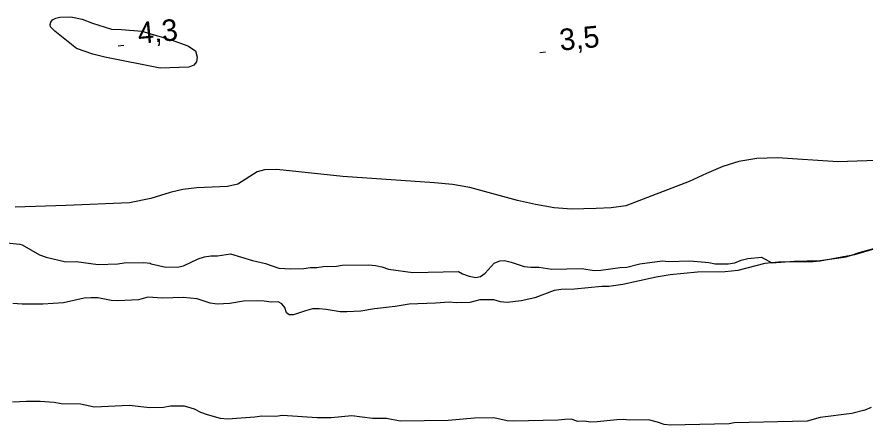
# Model space of a CAD drawing. Extents: x 336540 to 340074, y 5572036 to 5573747.
# Drawn here: x 336745.5 to 336863.5, y 5572306.6 to 5572363.4 of the extents above; entities that cross this region are included whole.
import ezdxf

# ---------------------------------------------------------------- set-up
doc = ezdxf.new("R2010")
doc.units = 0
for name, color, linetype in [('Niveau 2', 7, 'Continuous'), ('Niveau 3', 7, 'Continuous'), ('Niveau 4', 7, 'Continuous')]:
    doc.layers.add(name, color=color, linetype=linetype)

msp = doc.modelspace()

# ---------------------------------------------------------------- linework, layer by layer
at = {"layer": 'Niveau 2'}
for points in [[(336765.47, 5572356.26), (336757.74, 5572357.77), (336756.06, 5572358.18), (336753.83, 5572358.98), (336750.8, 5572361.38), (336750.2, 5572361.99), (336750.14, 5572362.3), (336750.22, 5572362.63), (336750.49, 5572362.97), (336750.92, 5572363.21), (336751.5, 5572363.32), (336753, 5572363.37), (336754.61, 5572363.05), (336756.02, 5572362.49), (336758.7, 5572361.66), (336760.09, 5572361.64), (336762.91, 5572361.4), (336766.97, 5572360.19), (336769.3, 5572359.34), (336770.34, 5572358.64), (336770.59, 5572357.75), (336770.57, 5572357.45), (336770.48, 5572357.14), (336770.14, 5572356.64), (336769.43, 5572356.39), (336765.47, 5572356.26)], [(336869.13, 5572343.53), (336859.69, 5572343.22), (336851.31, 5572343.74), (336848.43, 5572343.65), (336845.93, 5572343.25), (336843.7, 5572342.54), (336841.44, 5572341.6), (336839.04, 5572340.48), (336830.2, 5572337.08), (336828.17, 5572336.82), (336826.08, 5572336.71), (336822.65, 5572336.62), (336820.23, 5572336.79), (336817.64, 5572337.24), (336815.13, 5572337.82), (336808.53, 5572339.61), (336806.11, 5572340.03), (336803.61, 5572340.28), (336790.87, 5572341.18), (336781.69, 5572342.12), (336779.98, 5572342.09), (336778.96, 5572341.82), (336776.26, 5572340.08), (336774.82, 5572339.76), (336770.57, 5572339.58), (336768.61, 5572339.34), (336766.86, 5572338.94), (336764.17, 5572338.12), (336761.18, 5572337.49), (336752.35, 5572337.1), (336745.28, 5572336.91)], [(336864.83, 5572331.07), (336862.02, 5572330.27), (336857.23, 5572329.37), (336856.28, 5572329.29), (336851.47, 5572329.24), (336850.51, 5572329.16), (336849.55, 5572329.03), (336845.79, 5572328.09), (336844.04, 5572327.88), (336840.2, 5572327.85), (336836.36, 5572327.48), (336834.45, 5572327.16), (336829.78, 5572326.14), (336827.86, 5572325.87), (336826.9, 5572325.85), (336823.07, 5572325.48), (336821.2, 5572325.44), (336820.25, 5572325.31), (336817.56, 5572324.28), (336815.65, 5572323.84), (336813.73, 5572323.63), (336812.77, 5572323.72), (336811.85, 5572323.98), (336809.93, 5572324), (336808.53, 5572323.63), (336806.61, 5572323.58), (336805.64, 5572323.67), (336803.73, 5572323.52), (336800.06, 5572323.38), (336798.14, 5572323.05), (336795.26, 5572322.76), (336793.35, 5572322.43), (336791.43, 5572322.33), (336790.47, 5572322.31), (336788.54, 5572322.66), (336787.58, 5572322.75), (336786.62, 5572322.73), (336785.66, 5572322.48), (336783.98, 5572321.88), (336783.41, 5572321.92), (336783.01, 5572322.2), (336782.77, 5572322.93), (336782.36, 5572323.42), (336781.85, 5572323.7), (336780.89, 5572323.67), (336779.92, 5572323.82), (336778.96, 5572323.86), (336777.04, 5572323.81), (336775.13, 5572323.49)], [(336775.13, 5572323.49), (336773.38, 5572323.39), (336772.41, 5572323.54), (336770.59, 5572324.12), (336768.66, 5572324.3), (336765.78, 5572324.23), (336763.74, 5572324.36), (336762.45, 5572323.99), (336759.57, 5572323.87), (336758.61, 5572323.9), (336756.79, 5572324.25), (336755.83, 5572324.29), (336754.87, 5572324.21), (336752.01, 5572323.58), (336749.13, 5572323.4), (336746.24, 5572323.39), (336744.94, 5572323.47)], [(336864.33, 5572309), (336863.44, 5572308.64), (336861.64, 5572308.15), (336857.24, 5572307.6), (336855.44, 5572307.11), (336845.26, 5572306.87), (336844.58, 5572306.74), (336836.44, 5572306.56), (336835.54, 5572306.65), (336834.62, 5572306.97), (336833.37, 5572307.28), (336830.77, 5572307.22), (336829.86, 5572307.31), (336828.96, 5572307.29), (336826.25, 5572307), (336825.35, 5572306.98), (336824.44, 5572307.08), (336823.53, 5572307.06), (336822.62, 5572307.37), (336821.72, 5572307.35), (336820.82, 5572307.22), (336814.6, 5572307.08), (336813.69, 5572307.17), (336811.87, 5572307.58), (336809.16, 5572307.52), (336805.51, 5572307.18), (336798.84, 5572307.09), (336796.91, 5572307.49), (336794.99, 5572307.45), (336792.09, 5572307.84), (336789.21, 5572307.55), (336787.29, 5572307.56), (336782.47, 5572307.9), (336781.52, 5572307.77), (336779.59, 5572307.78), (336778.63, 5572307.64), (336774.79, 5572307.39), (336773.83, 5572307.48), (336772.01, 5572308), (336771.09, 5572308.32), (336770.24, 5572308.75), (336768.81, 5572309.17), (336766.89, 5572309.19), (336765.93, 5572308.99), (336764.01, 5572308.95), (336761.12, 5572309.28), (336756.31, 5572309.06), (336754.38, 5572309.47), (336751.66, 5572309.52), (336750.7, 5572309.72), (336748.77, 5572309.85), (336746.85, 5572309.86), (336744.93, 5572309.76)]]:
    msp.add_lwpolyline(points, dxfattribs=at)
at = {"layer": 'Niveau 3'}
for p, q in [((336759.6, 5572359.37), (336760.4, 5572359.45)), ((336818.24, 5572358.43), (336819.04, 5572358.51))]:
    msp.add_line(p, q, dxfattribs=at)
at = {"layer": 'Niveau 4'}
for points in [[(336743.2, 5572332.03), (336745.92, 5572331.76), (336746.26, 5572331.65), (336748.67, 5572330.24), (336749.58, 5572329.92), (336752.31, 5572329.3), (336753.77, 5572329.34), (336756.84, 5572328.93), (336759.55, 5572328.99), (336760.45, 5572329.13), (336763.16, 5572329.19), (336764.06, 5572329.1), (336764.18, 5572328.99), (336766.23, 5572328.56), (336768.04, 5572328.6), (336768.71, 5572328.73), (336770.71, 5572329.72), (336771.61, 5572329.97), (336772.51, 5572330.1), (336773.42, 5572330.13), (336775.22, 5572330.39), (336778.29, 5572329.45), (336780.11, 5572329.04)], [(336780.11, 5572329.04), (336781.93, 5572328.4), (336783.63, 5572328.3), (336785.44, 5572328.34), (336786.34, 5572328.48), (336787.24, 5572328.5), (336788.14, 5572328.63), (336789.95, 5572328.67), (336790.74, 5572328.8), (336794.47, 5572328.86), (336795.38, 5572328.77), (336796.28, 5572328.57), (336797.2, 5572328.25), (336800.61, 5572327.8), (336806.94, 5572327.95), (336807.51, 5572327.62), (336808.42, 5572327.3), (336809.33, 5572327.1), (336810.01, 5572327.23), (336810.67, 5572327.69), (336811.88, 5572329.08), (336812.67, 5572329.43), (336813.35, 5572329.45), (336814.25, 5572329.24), (336816.08, 5572328.61), (336816.98, 5572328.52), (336818.11, 5572328.54), (336819.93, 5572328.24), (336824.11, 5572328.34), (336825.83, 5572328.08), (336826.73, 5572328.1), (336829.43, 5572328.5), (336830.34, 5572328.52), (336832.14, 5572329.02), (336835.29, 5572329.43), (336836.2, 5572329.34), (336839.13, 5572329.4), (336841.75, 5572329.19), (336842.66, 5572328.98), (336844.47, 5572329.02), (336845.37, 5572329.16), (336846.27, 5572329.52), (336847.17, 5572329.76), (336849.08, 5572329.92), (336850.51, 5572329.16), (336853.64, 5572329.37), (336857.26, 5572329.46), (336860.87, 5572329.99), (336861.76, 5572330.24), (336862.66, 5572330.6), (336865.36, 5572331.34)]]:
    msp.add_lwpolyline(points, dxfattribs=at)

# ---------------------------------------------------------------- texts
at = {"layer": 'Niveau 3'}
for s, p in [('4,3    ', (336762.47, 5572359.61)), ('3,5    ', (336821.11, 5572358.67))]:
    msp.add_text(s, height=3, rotation=5.5424, dxfattribs=at).set_placement(p)

doc.saveas('drawing.dxf')
